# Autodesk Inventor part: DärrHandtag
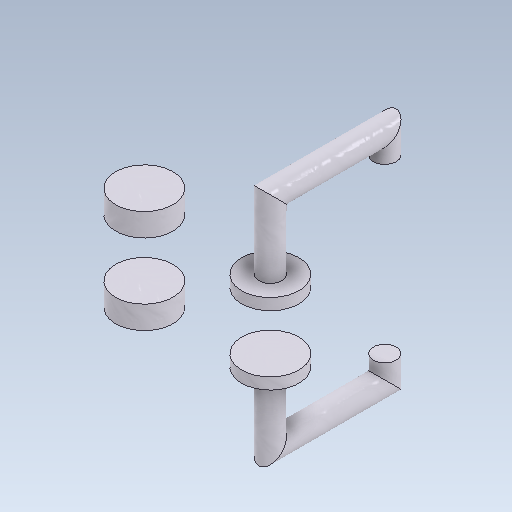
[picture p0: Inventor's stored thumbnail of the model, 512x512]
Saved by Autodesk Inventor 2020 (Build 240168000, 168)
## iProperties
Created: 2019-06
Part Number: DärrHandtag
Material: Aluminum 6061, Welded
Document SubType Name: Modeling
Designer: cl
Density: 2.7 g/cm^3
Appearance: Weld - Aluminum
Author: cl
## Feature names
1. Extrusion1
2. Extrusion2
3. Sweep1
4. Mirror1
## Parameters: d7 = 0, d10 = 0, d12 = 0, d18 = 0, d19 = 0, d20 = 25 mm
